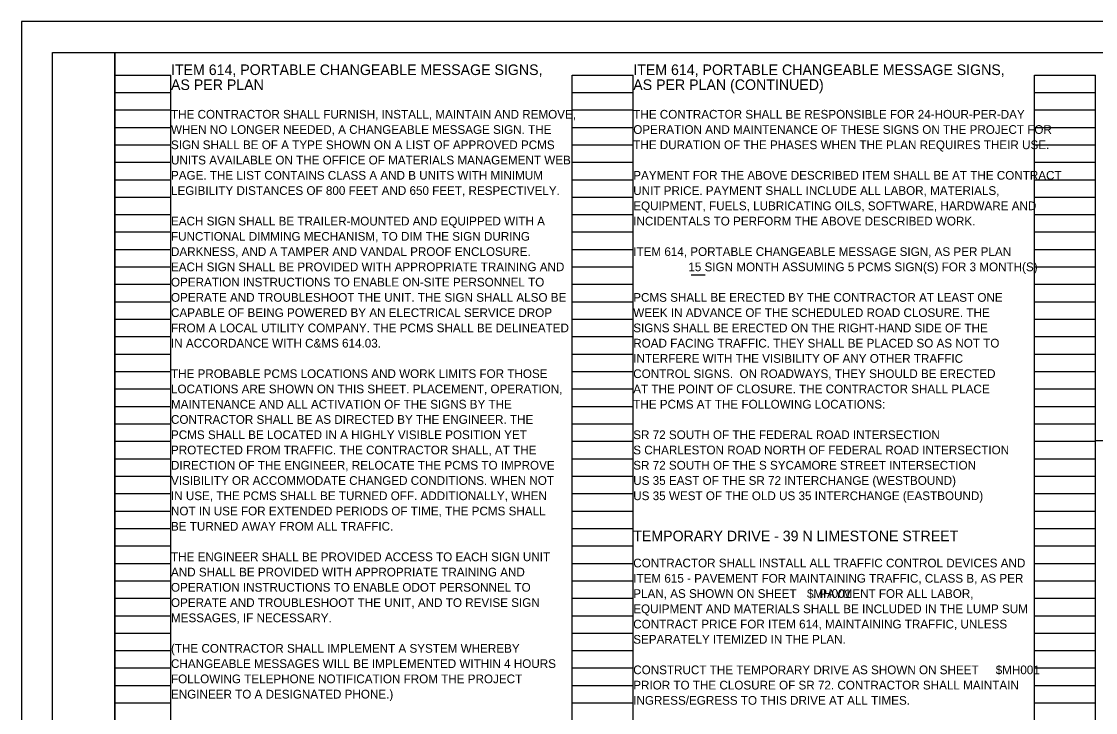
# Model space of a CAD drawing. Extents: x 0 to 69, y 0 to 22.
# Drawn here: x 35 to 52.24, y 10.91 to 22 of the extents above; entities that cross this region are included whole.
import ezdxf

# ---------------------------------------------------------------- set-up
doc = ezdxf.new("R2010")
doc.units = 0
for name, color, linetype in [('GM_X_City_Street', 7, 'Continuous'), ('GM_X_Corporation_Text', 7, 'Continuous'), ('SH_Border', 7, 'Continuous'), ('SH_Cut_Line', 7, 'Continuous'), ('SH_Text', 7, 'Continuous')]:
    doc.layers.add(name, color=color, linetype=linetype)

msp = doc.modelspace()

# ---------------------------------------------------------------- linework, layer by layer
at = {"layer": 'GM_X_City_Street'}
for p, q in [((36.5, 0.98), (36.5, 21.14)), ((36.5, 21.14), (37.4, 21.14)), ((37.4, 0.98), (37.4, 21.14)), ((43.84, 0.98), (43.84, 21.14)), ((43.84, 21.14), (44.82, 21.14)), ((44.82, 0.98), (44.82, 21.14)), ((51.26, 0.98), (51.26, 21.14)), ((51.26, 21.14), (52.24, 21.14)), ((52.24, 0.98), (52.24, 21.14)), ((36.5, 20.86), (37.4, 20.86)), ((43.84, 20.86), (44.82, 20.86)), ((51.26, 20.86), (52.24, 20.86)), ((36.5, 20.58), (37.4, 20.58)), ((43.84, 20.58), (44.82, 20.58)), ((51.26, 20.58), (52.24, 20.58)), ((36.5, 20.3), (37.4, 20.3)), ((43.84, 20.3), (44.82, 20.3)), ((51.26, 20.3), (52.24, 20.3)), ((36.5, 20.02), (37.4, 20.02)), ((43.84, 20.02), (44.82, 20.02)), ((51.26, 20.02), (52.24, 20.02)), ((36.5, 19.74), (37.4, 19.74)), ((43.84, 19.74), (44.82, 19.74)), ((51.26, 19.74), (52.24, 19.74)), ((36.5, 19.46), (37.4, 19.46)), ((43.84, 19.46), (44.82, 19.46)), ((51.26, 19.46), (52.24, 19.46)), ((36.5, 19.18), (37.4, 19.18)), ((43.84, 19.18), (44.82, 19.18)), ((51.26, 19.18), (52.24, 19.18)), ((36.5, 18.9), (37.4, 18.9)), ((43.84, 18.9), (44.82, 18.9)), ((51.26, 18.9), (52.24, 18.9)), ((36.5, 18.62), (37.4, 18.62)), ((43.84, 18.62), (44.82, 18.62)), ((51.26, 18.62), (52.24, 18.62)), ((36.5, 18.34), (37.4, 18.34)), ((43.84, 18.34), (44.82, 18.34)), ((51.26, 18.34), (52.24, 18.34)), ((36.5, 18.06), (37.4, 18.06)), ((43.84, 18.06), (44.82, 18.06)), ((51.26, 18.06), (52.24, 18.06)), ((36.5, 17.78), (37.4, 17.78)), ((43.84, 17.78), (44.82, 17.78)), ((51.26, 17.78), (52.24, 17.78)), ((36.5, 17.5), (37.4, 17.5)), ((43.84, 17.5), (44.82, 17.5)), ((51.26, 17.5), (52.24, 17.5)), ((36.5, 17.22), (37.4, 17.22)), ((43.84, 17.22), (44.82, 17.22)), ((51.26, 17.22), (52.24, 17.22)), ((36.5, 16.94), (37.4, 16.94)), ((43.84, 16.94), (44.82, 16.94)), ((51.26, 16.94), (52.24, 16.94)), ((36.5, 16.66), (37.4, 16.66)), ((43.84, 16.66), (44.82, 16.66)), ((51.26, 16.66), (52.24, 16.66)), ((36.5, 16.38), (37.4, 16.38)), ((43.84, 16.38), (44.82, 16.38)), ((51.26, 16.38), (52.24, 16.38)), ((36.5, 16.1), (37.4, 16.1)), ((43.84, 16.1), (44.82, 16.1)), ((51.26, 16.1), (52.24, 16.1)), ((36.5, 15.82), (37.4, 15.82)), ((43.84, 15.82), (44.82, 15.82)), ((51.26, 15.82), (52.24, 15.82)), ((36.5, 15.54), (37.4, 15.54)), ((43.84, 15.54), (44.82, 15.54)), ((51.26, 15.54), (52.24, 15.54)), ((36.5, 15.26), (37.4, 15.26)), ((43.84, 15.26), (44.82, 15.26)), ((51.26, 15.26), (52.24, 15.26)), ((36.5, 14.98), (37.4, 14.98)), ((43.84, 14.98), (44.82, 14.98)), ((51.26, 14.98), (52.24, 14.98)), ((36.5, 14.7), (37.4, 14.7)), ((43.84, 14.7), (44.82, 14.7)), ((51.26, 14.7), (52.24, 14.7)), ((36.5, 14.42), (37.4, 14.42)), ((43.84, 14.42), (44.82, 14.42)), ((51.26, 14.42), (52.24, 14.42)), ((36.5, 14.14), (37.4, 14.14)), ((43.84, 14.14), (44.82, 14.14)), ((51.26, 14.14), (52.24, 14.14)), ((36.5, 13.86), (37.4, 13.86)), ((43.84, 13.86), (44.82, 13.86)), ((51.26, 13.86), (52.24, 13.86)), ((36.5, 13.58), (37.4, 13.58)), ((43.84, 13.58), (44.82, 13.58)), ((51.26, 13.58), (52.24, 13.58)), ((36.5, 13.3), (37.4, 13.3)), ((43.84, 13.3), (44.82, 13.3)), ((51.26, 13.3), (52.24, 13.3)), ((36.5, 13.02), (37.4, 13.02)), ((43.84, 13.02), (44.82, 13.02)), ((51.26, 13.02), (52.24, 13.02)), ((36.5, 12.74), (37.4, 12.74)), ((43.84, 12.74), (44.82, 12.74)), ((51.26, 12.74), (52.24, 12.74)), ((36.5, 12.46), (37.4, 12.46)), ((43.84, 12.46), (44.82, 12.46)), ((51.26, 12.46), (52.24, 12.46)), ((36.5, 12.18), (37.4, 12.18)), ((43.84, 12.18), (44.82, 12.18)), ((51.26, 12.18), (52.24, 12.18)), ((36.5, 11.9), (37.4, 11.9)), ((43.84, 11.9), (44.82, 11.9)), ((51.26, 11.9), (52.24, 11.9)), ((36.5, 11.62), (37.4, 11.62)), ((43.84, 11.62), (44.82, 11.62)), ((51.26, 11.62), (52.24, 11.62)), ((36.5, 11.34), (37.4, 11.34)), ((43.84, 11.34), (44.82, 11.34)), ((51.26, 11.34), (52.24, 11.34)), ((36.5, 11.06), (37.4, 11.06)), ((43.84, 11.06), (44.82, 11.06)), ((51.26, 11.06), (52.24, 11.06))]:
    msp.add_line(p, q, dxfattribs=at)
at = {"layer": 'GM_X_Corporation_Text'}
msp.add_line((45.75, 17.933), (45.975, 17.933), dxfattribs=at)
at = {"layer": 'SH_Border'}
for points in [[(35.5, 21.5), (36.5, 21.5), (36.5, 0.5), (35.5, 0.5)], [(36.5, 21.5), (68.5, 21.5), (68.5, 0.5), (36.5, 0.5)]]:
    msp.add_lwpolyline(points, close=True, dxfattribs=at)
at = {"layer": 'SH_Cut_Line'}
msp.add_lwpolyline([(35, 0), (69, 0), (69, 22), (35, 22)], close=True, dxfattribs=at)
at = {"layer": 'SH_Text'}
msp.add_line((52.24, 15.273), (52.728, 15.273), dxfattribs=at)

# ---------------------------------------------------------------- texts
for s, height, p in [('ITEM 614, PORTABLE CHANGEABLE MESSAGE SIGNS,', 0.17, (37.4, 21.14)), ('ITEM 614, PORTABLE CHANGEABLE MESSAGE SIGNS,', 0.17, (44.82, 21.14)), ('AS PER PLAN', 0.17, (37.4, 20.9)), ('AS PER PLAN (CONTINUED)', 0.17, (44.82, 20.9)), ('THE CONTRACTOR SHALL FURNISH, INSTALL, MAINTAIN AND REMOVE, ', 0.14, (37.4, 20.44)), ('THE CONTRACTOR SHALL BE RESPONSIBLE FOR 24-HOUR-PER-DAY ', 0.14, (44.82, 20.44)), ('WHEN NO LONGER NEEDED, A CHANGEABLE MESSAGE SIGN. THE ', 0.14, (37.4, 20.195)), ('OPERATION AND MAINTENANCE OF THESE SIGNS ON THE PROJECT FOR ', 0.14, (44.82, 20.195)), ('SIGN SHALL BE OF A TYPE SHOWN ON A LIST OF APPROVED PCMS ', 0.14, (37.4, 19.95)), ('THE DURATION OF THE PHASES WHEN THE PLAN REQUIRES THEIR USE.', 0.14, (44.82, 19.95)), ('UNITS AVAILABLE ON THE OFFICE OF MATERIALS MANAGEMENT WEB ', 0.14, (37.4, 19.705)), ('PAGE. THE LIST CONTAINS CLASS A AND B UNITS WITH MINIMUM ', 0.14, (37.4, 19.46)), ('PAYMENT FOR THE ABOVE DESCRIBED ITEM SHALL BE AT THE CONTRACT ', 0.14, (44.82, 19.46)), ('LEGIBILITY DISTANCES OF 800 FEET AND 650 FEET, RESPECTIVELY.', 0.14, (37.4, 19.215)), ('UNIT PRICE. PAYMENT SHALL INCLUDE ALL LABOR, MATERIALS, ', 0.14, (44.82, 19.215)), ('EQUIPMENT, FUELS, LUBRICATING OILS, SOFTWARE, HARDWARE AND ', 0.14, (44.82, 18.97)), ('EACH SIGN SHALL BE TRAILER-MOUNTED AND EQUIPPED WITH A ', 0.14, (37.4, 18.725)), ('INCIDENTALS TO PERFORM THE ABOVE DESCRIBED WORK.', 0.14, (44.82, 18.725)), ('FUNCTIONAL DIMMING MECHANISM, TO DIM THE SIGN DURING ', 0.14, (37.4, 18.48)), ('DARKNESS, AND A TAMPER AND VANDAL PROOF ENCLOSURE. ', 0.14, (37.4, 18.235)), ('ITEM 614, PORTABLE CHANGEABLE MESSAGE SIGN, AS PER PLAN ', 0.14, (44.82, 18.235)), ('EACH SIGN SHALL BE PROVIDED WITH APPROPRIATE TRAINING AND ', 0.14, (37.4, 17.99)), ('                 15 SIGN MONTH ASSUMING 5 PCMS SIGN(S) FOR 3 MONTH(S)', 0.14, (44.82, 17.99)), ('OPERATION INSTRUCTIONS TO ENABLE ON-SITE PERSONNEL TO', 0.14, (37.4, 17.745)), ('OPERATE AND TROUBLESHOOT THE UNIT. THE SIGN SHALL ALSO BE ', 0.14, (37.4, 17.5)), ('PCMS SHALL BE ERECTED BY THE CONTRACTOR AT LEAST ONE ', 0.14, (44.82, 17.5)), ('CAPABLE OF BEING POWERED BY AN ELECTRICAL SERVICE DROP ', 0.14, (37.4, 17.255)), ('WEEK IN ADVANCE OF THE SCHEDULED ROAD CLOSURE. THE ', 0.14, (44.82, 17.255)), ('FROM A LOCAL UTILITY COMPANY. THE PCMS SHALL BE DELINEATED ', 0.14, (37.4, 17.01)), ('SIGNS SHALL BE ERECTED ON THE RIGHT-HAND SIDE OF THE ', 0.14, (44.82, 17.01)), ('IN ACCORDANCE WITH C&MS 614.03.', 0.14, (37.4, 16.765)), ('ROAD FACING TRAFFIC. THEY SHALL BE PLACED SO AS NOT TO ', 0.14, (44.82, 16.765)), ('INTERFERE WITH THE VISIBILITY OF ANY OTHER TRAFFIC ', 0.14, (44.82, 16.52)), ('THE PROBABLE PCMS LOCATIONS AND WORK LIMITS FOR THOSE ', 0.14, (37.4, 16.275)), ('CONTROL SIGNS.  ON ROADWAYS, THEY SHOULD BE ERECTED ', 0.14, (44.82, 16.275)), ('LOCATIONS ARE SHOWN ON THIS SHEET. PLACEMENT, OPERATION, ', 0.14, (37.4, 16.03)), ('AT THE POINT OF CLOSURE. THE CONTRACTOR SHALL PLACE ', 0.14, (44.82, 16.03)), ('MAINTENANCE AND ALL ACTIVATION OF THE SIGNS BY THE ', 0.14, (37.4, 15.785)), ('THE PCMS AT THE FOLLOWING LOCATIONS:', 0.14, (44.82, 15.785)), ('CONTRACTOR SHALL BE AS DIRECTED BY THE ENGINEER. THE ', 0.14, (37.4, 15.54)), ('PCMS SHALL BE LOCATED IN A HIGHLY VISIBLE POSITION YET', 0.14, (37.4, 15.295)), ('SR 72 SOUTH OF THE FEDERAL ROAD INTERSECTION', 0.14, (44.82, 15.295)), ('PROTECTED FROM TRAFFIC. THE CONTRACTOR SHALL, AT THE ', 0.14, (37.4, 15.05)), ('S CHARLESTON ROAD NORTH OF FEDERAL ROAD INTERSECTION', 0.14, (44.82, 15.05)), ('DIRECTION OF THE ENGINEER, RELOCATE THE PCMS TO IMPROVE ', 0.14, (37.4, 14.805)), ('SR 72 SOUTH OF THE S SYCAMORE STREET INTERSECTION', 0.14, (44.82, 14.805)), ('VISIBILITY OR ACCOMMODATE CHANGED CONDITIONS. WHEN NOT ', 0.14, (37.4, 14.56)), ('US 35 EAST OF THE SR 72 INTERCHANGE (WESTBOUND)', 0.14, (44.82, 14.56)), ('IN USE, THE PCMS SHALL BE TURNED OFF. ADDITIONALLY, WHEN ', 0.14, (37.4, 14.315)), ('US 35 WEST OF THE OLD US 35 INTERCHANGE (EASTBOUND)', 0.14, (44.82, 14.315)), ('NOT IN USE FOR EXTENDED PERIODS OF TIME, THE PCMS SHALL ', 0.14, (37.4, 14.07)), ('BE TURNED AWAY FROM ALL TRAFFIC.', 0.14, (37.4, 13.825)), ('TEMPORARY DRIVE - 39 N LIMESTONE STREET', 0.17, (44.82, 13.655)), ('THE ENGINEER SHALL BE PROVIDED ACCESS TO EACH SIGN UNIT ', 0.14, (37.4, 13.335)), ('CONTRACTOR SHALL INSTALL ALL TRAFFIC CONTROL DEVICES AND ', 0.14, (44.82, 13.235)), ('AND SHALL BE PROVIDED WITH APPROPRIATE TRAINING AND ', 0.14, (37.4, 13.09)), ('ITEM 615 - PAVEMENT FOR MAINTAINING TRAFFIC, CLASS B, AS PER ', 0.14, (44.82, 12.99)), ('OPERATION INSTRUCTIONS TO ENABLE ODOT PERSONNEL TO ', 0.14, (37.4, 12.845)), ('PLAN, AS SHOWN ON SHEET     . PAYMENT FOR ALL LABOR, ', 0.14, (44.82, 12.745)), ('$MH001', 0.14, (47.609, 12.745)), ('OPERATE AND TROUBLESHOOT THE UNIT, AND TO REVISE SIGN ', 0.14, (37.4, 12.6)), ('EQUIPMENT AND MATERIALS SHALL BE INCLUDED IN THE LUMP SUM ', 0.14, (44.82, 12.5)), ('MESSAGES, IF NECESSARY.', 0.14, (37.4, 12.355)), ('CONTRACT PRICE FOR ITEM 614, MAINTAINING TRAFFIC, UNLESS ', 0.14, (44.82, 12.255)), ('SEPARATELY ITEMIZED IN THE PLAN.', 0.14, (44.82, 12.01)), ('(THE CONTRACTOR SHALL IMPLEMENT A SYSTEM WHEREBY ', 0.14, (37.4, 11.865)), ('CHANGEABLE MESSAGES WILL BE IMPLEMENTED WITHIN 4 HOURS ', 0.14, (37.4, 11.62)), ('CONSTRUCT THE TEMPORARY DRIVE AS SHOWN ON SHEET  ', 0.14, (44.82, 11.52)), ('$MH001', 0.14, (50.638, 11.52)), ('FOLLOWING TELEPHONE NOTIFICATION FROM THE PROJECT ', 0.14, (37.4, 11.375)), ('PRIOR TO THE CLOSURE OF SR 72. CONTRACTOR SHALL MAINTAIN ', 0.14, (44.82, 11.275)), ('ENGINEER TO A DESIGNATED PHONE.)', 0.14, (37.4, 11.13)), ('INGRESS/EGRESS TO THIS DRIVE AT ALL TIMES.', 0.14, (44.82, 11.03))]:
    msp.add_text(s, height=height, dxfattribs=at).set_placement(p)

doc.saveas('drawing.dxf')
